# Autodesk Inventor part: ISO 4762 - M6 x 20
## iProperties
Created: 2007-03
Part Number: ISO 4762 - M6 x 20
Material: Acier inoxydable - 440C
Description: Vis cylindrique à six pans creux
Document SubType Name: Modeling
Standard: ISO 4762
Designer: EF
Standard Revision: Quatrième édition 2004-03-01
Standards Organization: ISO
Language: fr-FR
Size Designation: M6 x 20
Categories: <MemberInstance><Categories><Category DisplayName="Visserie" InternalName="e4da775c-781d-43d5-af7c-5136215cf5a6" Mnemonic="FSTN"><Category DisplayName="Vis" Int
Density: 1 g/cm^3
IsCustomPart: 0
Author: EF
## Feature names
1. Corps [Revolution]
2. Rainure [Extrusion]
3. Congé1 [Fillet]
4. Chanfrein1 [Chamfer]
5. Fillet2
